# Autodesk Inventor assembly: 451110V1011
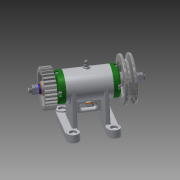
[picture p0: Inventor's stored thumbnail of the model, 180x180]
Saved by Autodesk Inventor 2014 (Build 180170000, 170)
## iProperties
Created: 2015-11
Part Number: 451110V1011
Document SubType Name: Assembly
Designer: user
Author: user
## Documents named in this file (16)
- C:\Users\user\Desktop\451110V1011\451110V1011.iam
- C:\Users\user\Desktop\451110V1011\451110V1011본체.ipt
- C:\Users\user\Desktop\451110V1011\커버.ipt
- C:\Users\user\Desktop\451110V1011\베어링 15 x 32 x 9.ipt
- C:\Users\user\Desktop\451110V1011\축.ipt
- C:\Users\user\Desktop\451110V1011\오일 실 15 25 7.ipt
- C:\Users\user\Desktop\451110V1011\볼트 M4 x 12.ipt
- C:\Users\user\Desktop\451110V1011\키 3 x 3 x 12.ipt
- C:\Users\user\Desktop\451110V1011\V벨트풀리.ipt
- C:\Users\user\Desktop\451110V1011\스퍼기어.ipt
- C:\Users\user\Desktop\451110V1011\와셔 8x17.ipt
- C:\Users\user\Desktop\451110V1011\스프링와셔 8.ipt
- C:\Users\user\Desktop\451110V1011\너트 M 8.ipt
- C:\Users\user\Desktop\451110V1011\와셔 6x11.5.ipt
- C:\Users\user\Desktop\451110V1011\볼트 M 6 x 8.ipt
- C:\Users\user\Desktop\451110V1011\니플 M 6 x 0.75.ipt
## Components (12 placed, 4 different names)
1. 451110V1011본체:1 — Insert:1, Mate:1, Mate:2, Mate:3, Insert:2, Insert:3, Insert:6, Insert:19
2. KS B 2023 6002 - 15 x 32 x 9:1 — Insert:2
3. KS B 2023 6002 - 15 x 32 x 9:2 — Insert:3, Insert:23
4. V벨트풀리:1 — Insert:14, Mate:7, Insert:15
5. ISO 4762 M4 x 12:4 — Insert:22
6. ISO 4762 M4 x 12:5
7. ISO 4762 M4 x 12:6
8. ISO 4762 M4 x 12:7
9. ISO 4762 M4 x 12:3 — Insert:21
10. ISO 4762 M4 x 12:8
11. ISO 4762 M4 x 12:9
12. ISO 4762 M4 x 12:10
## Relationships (14: Insert 10, Mate 4)
- Insert:1: 451110V1011본체:1
- Mate:1: 451110V1011본체:1
- Mate:2: 451110V1011본체:1
- Mate:3: 451110V1011본체:1
- Insert:2: 451110V1011본체:1 ↔ KS B 2023 6002 - 15 x 32 x 9:1
- Insert:3: 451110V1011본체:1 ↔ KS B 2023 6002 - 15 x 32 x 9:2
- Insert:6: 451110V1011본체:1
- Insert:14: V벨트풀리:1
- Mate:7: V벨트풀리:1
- Insert:15: V벨트풀리:1
- Insert:19: 451110V1011본체:1
- Insert:21: ISO 4762 M4 x 12:3
- Insert:22: ISO 4762 M4 x 12:4
- Insert:23: KS B 2023 6002 - 15 x 32 x 9:2
